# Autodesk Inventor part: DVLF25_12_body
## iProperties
Created: 2010-03
Part Number: DVLF25_12_body
Document SubType Name: Modeling
Designer: TB
Mass: 155.863 g
Surface Area: 494.446 cm^2
Volume: 155.863 cm^3
Density: 1 g/cm^3
Author: TB
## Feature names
1. Kropp [Revolution]
2. Chamfer
3. Extrusion2
4. Hole1
5. Revolution2
6. Hole2
7. Fillet1
8. Extrusion3
9. Hole3
